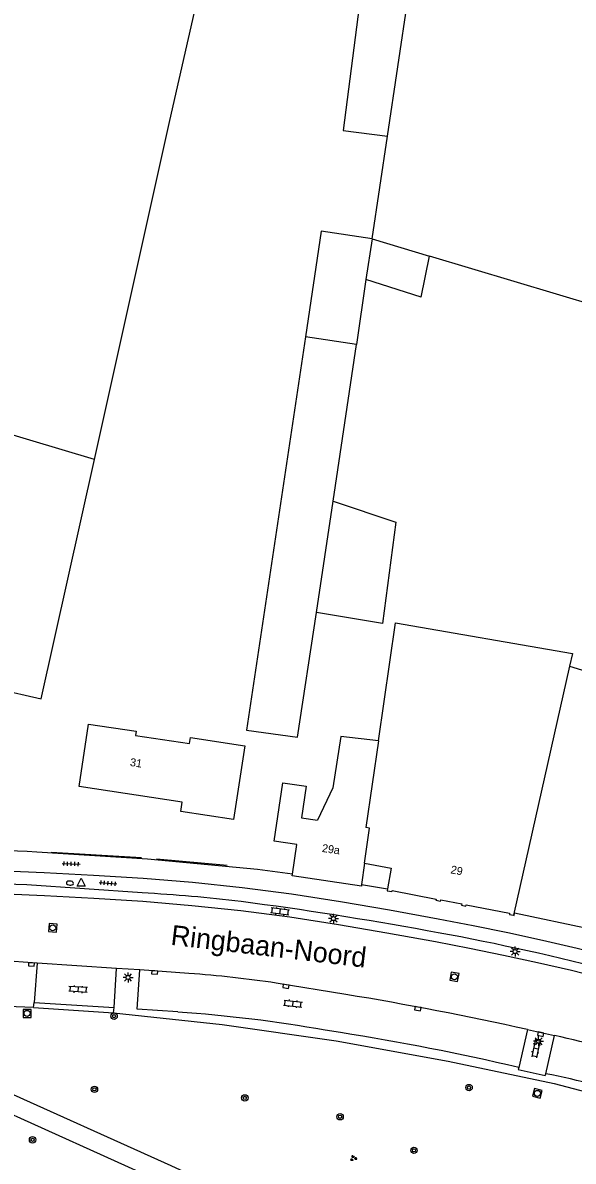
# Model space of a CAD drawing. Extents: x 132999 to 136000, y 398499 to 400501.
# Drawn here: x 134144.6 to 134213.4, y 398698.2 to 398840.4 of the extents above; entities that cross this region are included whole.
import ezdxf

# ---------------------------------------------------------------- set-up
doc = ezdxf.new("R2010")
doc.units = 0
for name, color, linetype in [('gg-afsc-muur', 7, 'Continuous'), ('gg-anno-huisnummerreeks BGT', 7, 'Continuous'), ('gg-anno-openbare ruimte label', 7, 'Continuous'), ('gg-bbg-gedigitaliseerde bebouwing', 7, 'Continuous'), ('gg-bbg-gedigitaliseerde bijgebouw', 7, 'Continuous'), ('gg-bbg-hoofdgebouw', 7, 'Continuous'), ('gg-bbg-luifel en loopbrug', 7, 'Continuous'), ('gg-bbg-tussenscheiding', 7, 'Continuous'), ('gg-knt-verharding', 7, 'Continuous'), ('gt-grn-groengrens', 7, 'Continuous'), ('gt-symb-boom', 7, 'Continuous'), ('gt-symb-brandkraan', 7, 'Continuous'), ('gt-symb-groenvak', 7, 'Continuous'), ('gt-symb-klinker verharding', 7, 'Continuous'), ('gt-symb-kolk', 7, 'Continuous'), ('gt-symb-lichtmast', 7, 'Continuous'), ('gt-symb-rioolschacht', 7, 'Continuous'), ('gt-symb-tegel verharding', 7, 'Continuous'), ('gt-symb-waterafsluiter', 7, 'Continuous')]:
    doc.layers.add(name, color=color, linetype=linetype)

# ---------------------------------------------------------------- blocks, each defined once
blk = doc.blocks.new('gt0-KOLK')
at = {"layer": 'gt-symb-kolk'}
blk.add_lwpolyline([(0, 0), (0.37, 0), (0.37, 0.4), (-0.38, 0.4), (-0.38, 0), (0, 0)], dxfattribs=at)
blk = doc.blocks.new('gt0-RS')
at = {"layer": 'gt-symb-rioolschacht'}
blk.add_lwpolyline([(-0.5, -0.5), (0.5, -0.5), (0.5, 0.5), (-0.5, 0.5)], close=True, dxfattribs=at)
blk.add_circle((0, 0), 0.375, dxfattribs=at)
blk = doc.blocks.new('gt0-BR')
at = {"layer": 'gt-symb-brandkraan'}
for centre, radius, start, end in [((-0.24, 0), 0.206, 107.5669, 252.4331), ((0.6, -2.66), 3, 106.892, 107.5669), ((0, -0.69), 0.938, 73.108, 106.892), ((-0.6, -2.66), 3, 72.4331, 73.108), ((0.24, 0), 0.206, 287.567, 72.4331), ((0.6, 2.66), 3, 252.4331, 253.108), ((0, 0.69), 0.938, 253.108, 286.8921), ((-0.6, 2.66), 3, 286.8921, 287.567)]:
    blk.add_arc(centre, radius, start, end, dxfattribs=at)
blk = doc.blocks.new('gt0-TEG1')
at = {"layer": 'gt-symb-tegel verharding'}
for p, q in [((-1.12, 0), (1.12, 0)), ((-0.9, -0.25), (-0.9, 0.25)), ((-0.45, -0.25), (-0.45, 0.25)), ((0, -0.25), (0, 0.25)), ((0.45, -0.25), (0.45, 0.25)), ((0.9, -0.25), (0.9, 0.25))]:
    blk.add_line(p, q, dxfattribs=at)
blk = doc.blocks.new('gt0-KL1')
at = {"layer": 'gt-symb-klinker verharding'}
for p, q in [((-1.15, 0.3), (1.15, 0.3)), ((-1, -0.3), (-1, 0.3)), ((-0.5, 0.3), (-0.5, 0.45)), ((0, -0.3), (0, 0.3)), ((0.5, 0.3), (0.5, 0.45)), ((1, -0.3), (1, 0.3)), ((-1.15, -0.3), (1.15, -0.3)), ((-0.5, -0.45), (-0.5, -0.3)), ((0.5, -0.45), (0.5, -0.3))]:
    blk.add_line(p, q, dxfattribs=at)
blk = doc.blocks.new('gt0-WAFSL')
at = {"layer": 'gt-symb-waterafsluiter'}
for p, q in [((-0.5, -0.33), (0, 0.67)), ((0, 0.67), (0.5, -0.33)), ((0.5, -0.33), (-0.5, -0.33))]:
    blk.add_line(p, q, dxfattribs=at)
blk = doc.blocks.new('gt0-LMAST')
at = {"layer": 'gt-symb-lichtmast'}
for p, q in [((-0.18, 0.17), (-0.45, 0.44)), ((-0.01, 0.25), (-0.01, 0.62)), ((0.17, 0.17), (0.44, 0.44)), ((-0.26, 0), (-0.63, 0)), ((-0.18, -0.18), (-0.45, -0.45)), ((-0.01, -0.25), (-0.01, -0.63)), ((0.44, -0.45), (0.17, -0.18)), ((0.24, 0), (0.62, 0))]:
    blk.add_line(p, q, dxfattribs=at)
blk.add_circle((-0.01, 0), 0.25, dxfattribs=at)
blk = doc.blocks.new('gt0-BOOM')
at = {"layer": 'gt-symb-boom'}
for radius in [0.4, 0.2]:
    blk.add_circle((0, 0), radius, dxfattribs=at)
blk = doc.blocks.new('gt0-GRVAK')
at = {"layer": 'gt-symb-groenvak'}
for p, q in [((-0.11, 0.19), (-0.23, 0.24)), ((-0.18, 0.15), (0.09, 0.15)), ((-0.09, 0.21), (-0.16, 0.32)), ((-0.05, 0.21), (-0.05, 0.39)), ((0, 0.21), (0.06, 0.32)), ((0.01, 0.19), (0.13, 0.24)), ((0.26, -0.05), (0.2, 0.06)), ((0.3, -0.05), (0.3, 0.13)), ((0.35, -0.05), (0.41, 0.06)), ((-0.24, -0.23), (-0.36, -0.18)), ((-0.32, -0.26), (-0.05, -0.26)), ((-0.23, -0.21), (-0.29, -0.09)), ((-0.18, -0.2), (-0.18, -0.02)), ((-0.14, -0.21), (-0.07, -0.09)), ((-0.12, -0.23), (0, -0.18)), ((0.24, -0.07), (0.12, -0.02)), ((0.17, -0.11), (0.44, -0.11)), ((0.37, -0.07), (0.49, -0.02))]:
    blk.add_line(p, q, dxfattribs=at)

msp = doc.modelspace()

# ---------------------------------------------------------------- linework, layer by layer
at = {"layer": 'gg-afsc-muur'}
for p, q in [((134148.18, 398736.8), (134159.47, 398736.11)), ((134161.34, 398735.97), (134170.16, 398735.14))]:
    msp.add_line(p, q, dxfattribs=at)
at = {"layer": 'gg-bbg-gedigitaliseerde bebouwing'}
for p, q in [((134163, 398828.18), (134172.85, 398871.31)), ((134153.58, 398785.83), (134163, 398828.18)), ((134188.28, 398813.39), (134190.19, 398826.24)), ((134219.26, 398804.09), (134195.44, 398811.24)), ((134146.94, 398755.95), (134153.58, 398785.83)), ((134212.95, 398760.03), (134254.18, 398747.15))]:
    msp.add_line(p, q, dxfattribs=at)
for points in [[(134189.06, 398750.67), (134191.19, 398765.43), (134213.33, 398761.61), (134212.95, 398760.03)], [(134151.67, 398744.98), (134152.85, 398752.78), (134158.79, 398751.88), (134158.71, 398751.36), (134165.48, 398750.34), (134165.6, 398751.1), (134172.37, 398750.08), (134170.97, 398740.85)], [(134189.06, 398750.67), (134184.36, 398751.24), (134183.37, 398744.83), (134181.46, 398740.77)], [(134176.04, 398738.17), (134177.11, 398745.44), (134180.05, 398745.01), (134179.45, 398741.08), (134181.46, 398740.77)]]:
    msp.add_lwpolyline(points, dxfattribs=at)
at = {"layer": 'gg-bbg-gedigitaliseerde bijgebouw'}
for p, q in [((134188.28, 398813.39), (134187.51, 398808.33)), ((134194.39, 398806.12), (134195.44, 398811.24)), ((134194.39, 398806.12), (134187.51, 398808.33)), ((134186.31, 398800.2), (134179.95, 398801.15)), ((134183.41, 398780.61), (134186.31, 398800.2))]:
    msp.add_line(p, q, dxfattribs=at)
for points in [[(134193.45, 398848.17), (134187.48, 398848.93), (134184.68, 398826.94), (134190.19, 398826.24)], [(134179.95, 398801.15), (134172.59, 398752.01), (134178.95, 398751.16), (134181.34, 398766.73)], [(134183.41, 398780.61), (134191.23, 398778.02), (134189.57, 398765.36), (134181.34, 398766.73)]]:
    msp.add_lwpolyline(points, dxfattribs=at)
at = {"layer": 'gg-bbg-hoofdgebouw'}
for p, q in [((134136.11, 398758.43), (134146.94, 398755.95)), ((134187.31, 398735.4), (134186.96, 398732.75))]:
    msp.add_line(p, q, dxfattribs=at)
for points in [[(134170.97, 398740.85), (134164.38, 398741.85), (134164.55, 398743.02), (134151.67, 398744.98)], [(134178.32, 398734.04), (134178.87, 398737.75), (134176.04, 398738.17)], [(134187.31, 398735.4), (134190.68, 398734.8), (134190.22, 398732.2)], [(134186.96, 398732.75), (134186.94, 398732.55), (134178.29, 398733.83), (134178.32, 398734.04)], [(134190.22, 398732.2), (134190.18, 398731.96), (134190.75, 398731.86), (134190.8, 398731.99), (134196.27, 398730.93), (134196.25, 398730.77), (134196.82, 398730.68), (134196.87, 398730.81), (134199.48, 398730.31), (134199.45, 398730.15), (134200, 398730.05), (134200.03, 398730.21), (134205.46, 398729.15), (134205.43, 398729), (134205.93, 398728.91)], [(134205.93, 398728.91), (134206.02, 398728.89), (134206.07, 398729.16)], [(134245.37, 398717.77), (134234.98, 398721.57), (134225.01, 398724.59), (134215.54, 398727.15), (134206.07, 398729.16)]]:
    msp.add_lwpolyline(points, dxfattribs=at)
at = {"layer": 'gg-bbg-luifel en loopbrug'}
msp.add_line((134187.51, 398808.33), (134186.31, 398800.2), dxfattribs=at)
msp.add_lwpolyline([(134188.28, 398813.39), (134181.93, 398814.34), (134179.95, 398801.15)], dxfattribs=at)
at = {"layer": 'gg-bbg-tussenscheiding'}
for p, q in [((134190.19, 398826.24), (134193.45, 398848.17)), ((134188.28, 398813.39), (134195.44, 398811.24)), ((134153.58, 398785.83), (134116.3, 398796.94)), ((134181.34, 398766.73), (134183.41, 398780.61)), ((134212.95, 398760.03), (134205.93, 398728.91)), ((134189.06, 398750.67), (134187.49, 398739.85))]:
    msp.add_line(p, q, dxfattribs=at)
msp.add_lwpolyline([(134187.31, 398735.4), (134187.94, 398739.78), (134187.49, 398739.85)], dxfattribs=at)
at = {"layer": 'gg-knt-verharding'}
for p, q in [((134159.55, 398731.7), (134145.16, 398732.69)), ((134186.96, 398732.75), (134190.22, 398732.2)), ((134146.43, 398722.92), (134141.83, 398723.23)), ((134146.43, 398722.92), (134146.04, 398718.02)), ((134156.36, 398722.26), (134146.43, 398722.92)), ((134156.05, 398717.36), (134156.36, 398722.26)), ((134159.27, 398722.07), (134156.36, 398722.26)), ((134165.39, 398721.63), (134159.27, 398722.07)), ((134185.01, 398719.01), (134176.31, 398720.43)), ((134146.04, 398718.02), (134156.05, 398717.36)), ((134184.33, 398714.25), (134182.4, 398714.54)), ((134207.69, 398714.64), (134206.59, 398709.88)), ((134207.69, 398714.64), (134211.07, 398713.89)), ((134209.97, 398709.11), (134211.07, 398713.89))]:
    msp.add_line(p, q, dxfattribs=at)
for points in [[(134178.32, 398734.04), (134173.96, 398734.62), (134160.2, 398735.9), (134146.39, 398736.8)], [(134142.39, 398734.44), (134147.29, 398734.24), (134153.49, 398733.91), (134159.68, 398733.52), (134165.86, 398733.02), (134172.04, 398732.37), (134178.19, 398731.57), (134184.32, 398730.62), (134190.44, 398729.57), (134196.54, 398728.47), (134200.9, 398727.62), (134205.25, 398726.73), (134209.58, 398725.78), (134213.9, 398724.77), (134218.21, 398723.69), (134222.51, 398722.57), (134226.78, 398721.38), (134231.04, 398720.14)], [(134242.36, 398713.15), (134240.59, 398713.6), (134229.93, 398717.41), (134225.77, 398718.64), (134221.59, 398719.82), (134217.39, 398720.93), (134213.17, 398721.98), (134208.95, 398722.97), (134204.7, 398723.89), (134200.45, 398724.76), (134196.18, 398725.58), (134190.13, 398726.67), (134184.07, 398727.71), (134177.99, 398728.65), (134171.89, 398729.44), (134165.77, 398730.09), (134159.64, 398730.6), (134153.51, 398731.01), (134147.37, 398731.34), (134142.61, 398731.53)], [(134164.02, 398716.82), (134158.93, 398717.16), (134159.27, 398722.07)], [(134206.59, 398709.88), (134206.53, 398709.64), (134209.91, 398708.87), (134209.97, 398709.11)], [(134140.91, 398707.64), (134163.14, 398697.63), (134177, 398691.23), (134212.46, 398674.45)], [(134139.96, 398705.51), (134162.13, 398695.52), (134176.15, 398689.08), (134211.45, 398672.33), (134220.85, 398668.63), (134223.71, 398667.7), (134223.75, 398667.78), (134225.59, 398667.03), (134228, 398665.92)]]:
    msp.add_lwpolyline(points, dxfattribs=at)
for centre, radius, start, end in [((134130.01, 398385.05), 352.13, 87.3332, 93.6271), ((134131.58, 398438.4), 294.61, 87.3577, 95.9708), ((134149.9, 398550.27), 181.68, 83.0446, 86.9579), ((134113.57, 398283.11), 451.29, 79.585, 82.5728), ((134140.27, 398420.63), 311.22, 75.6548, 79.8428), ((134156.01, 398586.02), 135.93, 81.41, 86.0443), ((134114.92, 398294.84), 429.92, 77.5378, 80.6175), ((134151.84, 398542.86), 174.38, 79.9083, 85.9945), ((134137.78, 398417.85), 300.03, 76.741, 81.0749), ((134165.66, 398513.73), 205.24, 73.6079, 77.2163), ((134186.89, 398593.48), 117.91, 72.5741, 78.7154)]:
    msp.add_arc(centre, radius, start, end, dxfattribs=at)
at = {"layer": 'gt-grn-groengrens'}
for p, q in [((134145.99, 398717.36), (134146.04, 398718.02)), ((134145.99, 398717.36), (134155.98, 398716.7)), ((134155.98, 398716.7), (134156.05, 398717.36))]:
    msp.add_line(p, q, dxfattribs=at)
for points in [[(134145.99, 398717.36), (134141.62, 398717.53), (134141.63, 398717.68)], [(134155.98, 398716.7), (134169.55, 398715.26), (134183.8, 398713.2), (134197.8, 398710.68), (134211.03, 398707.89), (134224.47, 398704.36), (134237.75, 398699.54), (134240.23, 398704.81)]]:
    msp.add_lwpolyline(points, dxfattribs=at)

# ---------------------------------------------------------------- block references
at = {"layer": 'gt-symb-boom'}
for p in [(134156.04, 398716.3), (134153.59, 398707.16), (134200.39, 398707.38), (134172.38, 398706.09), (134184.28, 398703.73), (134145.86, 398700.85), (134193.51, 398699.54)]:
    msp.add_blockref('gt0-BOOM', p, dxfattribs=at)
at = {"layer": 'gt-symb-brandkraan', "rotation": -5.163306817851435}
msp.add_blockref('gt0-BR', (134150.53, 398732.92), dxfattribs=at)
at = {"layer": 'gt-symb-groenvak'}
msp.add_blockref('gt0-GRVAK', (134185.94, 398698.55), dxfattribs=at)
at = {"layer": 'gt-symb-klinker verharding'}
for p, rotation in [((134176.76, 398729.37), 172.59081596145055), ((134151.54, 398719.64), 176.38792501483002), ((134178.39, 398717.86), -6.371822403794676), ((134208.75, 398712.29), -101.82670392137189)]:
    msp.add_blockref('gt0-KL1', p, dxfattribs=dict(at, rotation=rotation))
at = {"layer": 'gt-symb-kolk'}
for p, rotation in [((134145.73, 398722.95), 175.86946138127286), ((134161.13, 398721.95), 176.27357411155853), ((134177.54, 398720.22), 170.1513776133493), ((134194.02, 398717.43), 169.39794171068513), ((134209.38, 398714.25), 167.172876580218)]:
    msp.add_blockref('gt0-KOLK', p, dxfattribs=dict(at, rotation=rotation))
at = {"layer": 'gt-symb-lichtmast'}
for p in [(134183.46, 398728.48), (134206.15, 398724.37), (134157.8, 398721.13), (134209.09, 398713.17)]:
    msp.add_blockref('gt0-LMAST', p, dxfattribs=at)
at = {"layer": 'gt-symb-rioolschacht'}
for p, rotation in [((134148.38, 398727.33), -5.106241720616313), ((134198.56, 398721.21), -10.545734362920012), ((134208.93, 398706.65), 75.93596328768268)]:
    msp.add_blockref('gt0-RS', p, dxfattribs=dict(at, rotation=rotation))
msp.add_blockref('gt0-RS', (134145.17, 398716.64), dxfattribs=at)
at = {"layer": 'gt-symb-tegel verharding'}
for p, rotation in [((134150.68, 398735.32), -1.9492541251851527), ((134155.29, 398732.91), -4.302011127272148)]:
    msp.add_blockref('gt0-TEG1', p, dxfattribs=dict(at, rotation=rotation))
at = {"layer": 'gt-symb-waterafsluiter'}
msp.add_blockref('gt0-WAFSL', (134151.94, 398732.87), dxfattribs=at)

# ---------------------------------------------------------------- texts
at = {"layer": 'gg-anno-huisnummerreeks BGT'}
for s, rotation, p in [('31', 351.4, (134157.99, 398747.56)), ('29a', 351.6, (134181.97, 398736.82)), ('29', 349.1, (134198.03, 398734.15))]:
    msp.add_text(s, height=1, rotation=rotation, dxfattribs=at).set_placement(p)
at = {"layer": 'gg-anno-openbare ruimte label'}
msp.add_text('Ringbaan-Noord', height=2.5, rotation=353.3, dxfattribs=at).set_placement((134163.04, 398725.22))

doc.saveas('drawing.dxf')
